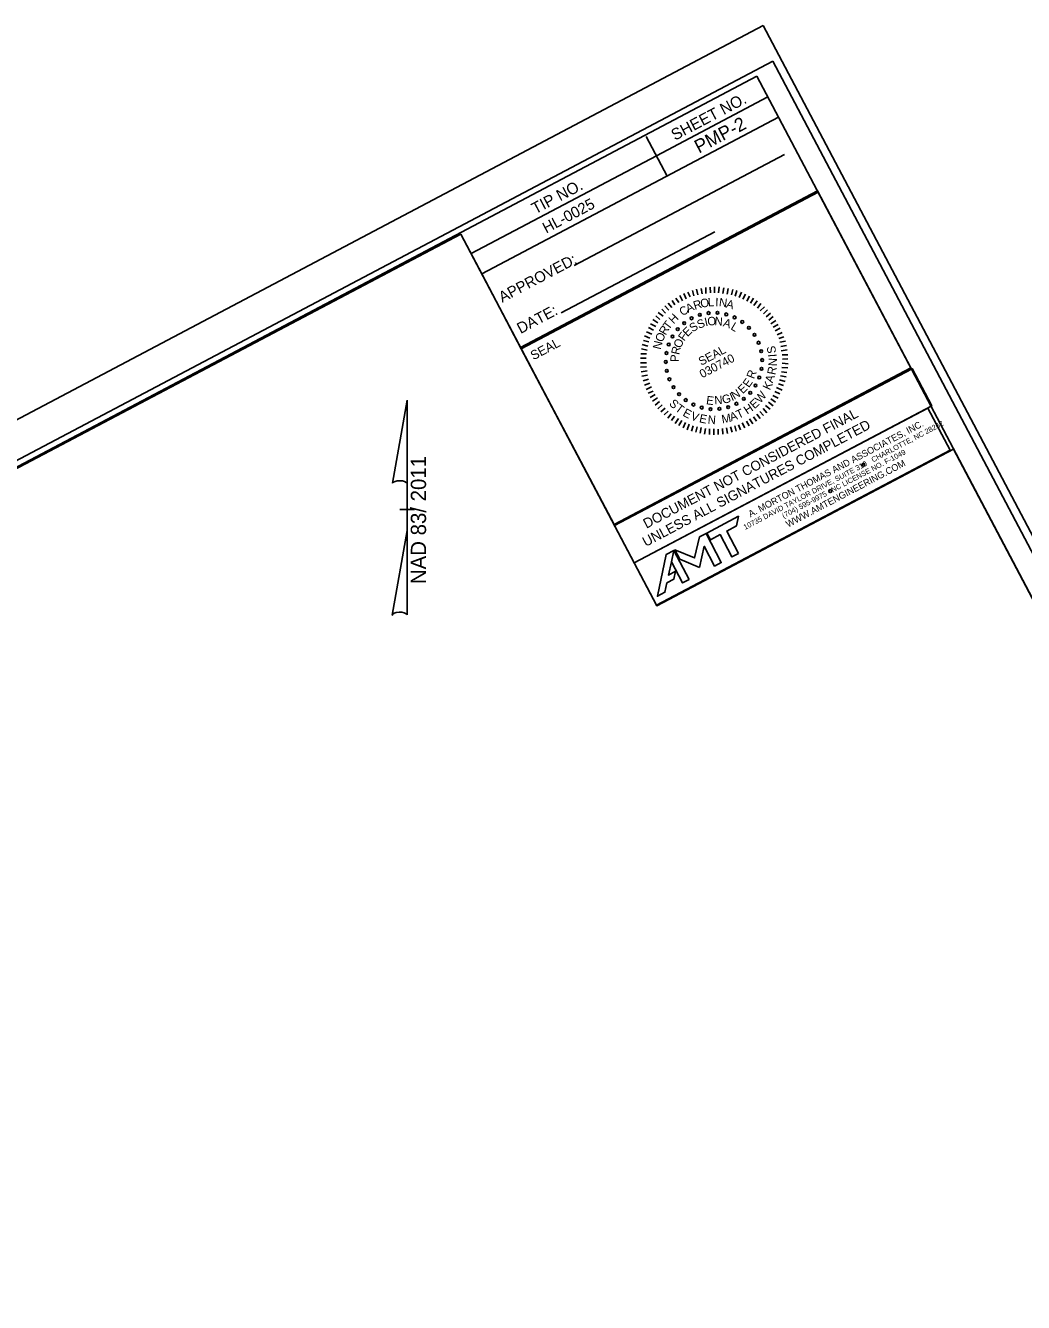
# Model space of a CAD drawing. Extents: x 1487176 to 1489663, y 497841 to 500965.
# Drawn here: x 1488420 to 1488976, y 499031 to 499742 of the extents above; entities that cross this region are included whole.
import ezdxf

# ---------------------------------------------------------------- set-up
doc = ezdxf.new("R2010")
doc.units = 0
for name, color, linetype in [('Default', 7, 'Continuous'), ('DEV TUBULAR MARKER PLAN VIEW CELL', 7, 'Continuous'), ('MARK LEFT TURN ARROW CELL', 7, 'Continuous'), ('MARK STRAIGHT ARROW CELL', 7, 'Continuous'), ('Prop Mkg Skp Wht', 7, 'Continuous'), ('Prop Mkg Solid Dbl Yel Rpm 80ft', 7, 'Continuous'), ('Prop Mkg Solid White Lane Line', 7, 'Continuous'), ('Prop Mkg Solid White Stop Bar', 7, 'Continuous'), ('Prop Paint Stripe', 7, 'Continuous'), ('Scratch_Level_1', 7, 'Continuous'), ('Scratch_Level_4', 7, 'Continuous'), ('Scratch_Level_6', 7, 'Continuous')]:
    doc.layers.add(name, color=color, linetype=linetype)

msp = doc.modelspace()

# ---------------------------------------------------------------- linework, layer by layer
at = {"layer": 'Default'}
for p, q in [((1488827.5, 499712.99), (1488827.5, 499712.99)), ((1488827.5, 499712.99), (1488827.5, 499712.99)), ((1488827.5, 499712.99), (1488827.5, 499712.99)), ((1488827.5, 499712.99), (1488827.5, 499712.99)), ((1488827.5, 499712.99), (1488827.5, 499712.99)), ((1488827.5, 499712.99), (1488827.5, 499712.99)), ((1488827.5, 499712.99), (1488827.5, 499712.99)), ((1488827.5, 499712.99), (1488827.5, 499712.99)), ((1488777.02, 499658.15), (1488765.37, 499680.23)), ((1488717.98, 499582), (1488803.58, 499627.15))]:
    msp.add_line(p, q, dxfattribs=at)
msp.add_lwpolyline([(1488695.45, 499562.62), (1488860.8, 499649.92), (1488912.82, 499551.41), (1488747.47, 499464.1)], close=True, dxfattribs=at)
at = {"layer": 'DEV TUBULAR MARKER PLAN VIEW CELL'}
msp.add_lwpolyline([(1488120.36, 498369.24), (1487949.53, 498194.25), (1487512.58, 499019.67), (1488662.1, 499625.77), (1488771.25, 499418.79), (1488936.61, 499505.98), (1489317.21, 498785.18), (1488242.69, 498217.81)], close=True, dxfattribs=at)
at = {"layer": 'MARK LEFT TURN ARROW CELL'}
msp.add_lwpolyline([(1488758.67, 499442.65), (1488922.34, 499528.95), (1488934.76, 499505.4), (1488771.09, 499419.09)], close=True, dxfattribs=at)
at = {"layer": 'MARK STRAIGHT ARROW CELL'}
msp.add_lwpolyline([(1488830.57, 499741.98), (1487342.38, 498956.18), (1487854.09, 497987.08), (1489342.28, 498772.88)], close=True, dxfattribs=at)
at = {"layer": 'Prop Mkg Skp Wht'}
msp.add_lwpolyline([(1488747.71, 499463.43), (1488913.52, 499550.87), (1488924.48, 499530.08), (1488758.67, 499442.65)], close=True, dxfattribs=at)
at = {"layer": 'Prop Mkg Solid Dbl Yel Rpm 80ft'}
for p, q in [((1488830.57, 499741.98), (1488830.57, 499741.98)), ((1488835.94, 499722.2), (1488835.94, 499722.2))]:
    msp.add_line(p, q, dxfattribs=at)
at = {"layer": 'Prop Mkg Solid White Lane Line'}
for p, q in [((1488771.08, 499669.42), (1488833.21, 499702.18)), ((1488673.74, 499603.7), (1488839.15, 499690.91)), ((1488777.02, 499658.15), (1488765.37, 499680.23)), ((1488667.8, 499614.97), (1488771.08, 499669.42)), ((1488673.74, 499603.7), (1488662.1, 499625.77)), ((1488695.75, 499561.97), (1488673.74, 499603.7))]:
    msp.add_line(p, q, dxfattribs=at)
for points in [[(1488826.93, 499713.69), (1487500.49, 499013.3), (1487990.76, 498084.79), (1489317.21, 498785.18)], [(1488695.75, 499561.97), (1488861.15, 499649.19), (1488913.11, 499550.65), (1488747.71, 499463.43)], [(1488758.67, 499442.65), (1488922.34, 499528.95), (1488934.76, 499505.4), (1488771.09, 499419.09)]]:
    msp.add_lwpolyline(points, close=True, dxfattribs=at)
for points in [[(1488816.84, 499447.97), (1488810.26, 499460.44), (1488815.64, 499463.27), (1488816.78, 499468.62), (1488799.18, 499459.33), (1488801.13, 499455.62), (1488806.55, 499458.48), (1488813.13, 499446.01), (1488816.84, 499447.97)], [(1488795.15, 499440.17), (1488797.7, 499451.99), (1488803.52, 499440.94), (1488807.23, 499442.9), (1488798.7, 499459.08), (1488794.99, 499457.13), (1488792.38, 499445.43), (1488781.32, 499449.92), (1488784.03, 499444.76), (1488795.15, 499440.17)], [(1488779.42, 499443.36), (1488780.84, 499449.67), (1488776.51, 499447.38), (1488771.6, 499424.11), (1488775.81, 499426.33), (1488776.9, 499431.55), (1488780.75, 499433.58), (1488781.78, 499438.03), (1488777.8, 499435.94), (1488779.42, 499443.36)], [(1488789.38, 499433.48), (1488780.84, 499449.67), (1488779.42, 499443.36), (1488785.66, 499431.53), (1488789.38, 499433.48)]]:
    msp.add_lwpolyline(points, dxfattribs=at)
for centre in [(1488886.42, 499497.36), (1488867.88, 499482.66)]:
    msp.add_circle(centre, 0.833, dxfattribs=at)
at = {"layer": 'Prop Mkg Solid White Stop Bar'}
for p, q in [((1488623.97, 499487.02), (1488632.17, 499533.37)), ((1488632.22, 499533.37), (1488632.17, 499533.37)), ((1488632.22, 499533.37), (1488632.17, 499533.37)), ((1488632.22, 499533.37), (1488632.22, 499485.57)), ((1488632.22, 499460.77), (1488632.22, 499486.97)), ((1488632.22, 499485.57), (1488632.22, 499486.92)), ((1488628.22, 499472.37), (1488628.17, 499472.37)), ((1488631.77, 499472.37), (1488628.22, 499472.37)), ((1488628.27, 499472.37), (1488636.27, 499472.37)), ((1488632.22, 499460.77), (1488623.87, 499413.52)), ((1488632.27, 499413.72), (1488632.22, 499460.77))]:
    msp.add_line(p, q, dxfattribs=at)
for centre, start_param, end_param in [((1488628.1, 499486.52), 0.216388, 2.908219), ((1488628.1, 499413.35), 0.201328, 3.141593)]:
    msp.add_ellipse(centre, major_axis=(4.23, -0.03), ratio=0.461098, start_param=start_param, end_param=end_param, dxfattribs=at)
at = {"layer": 'Prop Paint Stripe'}
msp.add_line((1488725.22, 499608.33), (1488842.52, 499670.19), dxfattribs=at)
at = {"layer": 'Scratch_Level_1'}
msp.add_lwpolyline([(1488835.94, 499722.2), (1487363.2, 498944.56), (1487856.23, 498010.83), (1489328.96, 498788.47)], close=True, dxfattribs=at)
at = {"layer": 'Scratch_Level_4'}
for p, q in [((1488786.37, 499592.78), (1488787.56, 499589.73)), ((1488788.65, 499593.56), (1488789.83, 499590.79)), ((1488791.14, 499594.45), (1488791.99, 499591.51)), ((1488793.48, 499595.12), (1488794.1, 499592.06)), ((1488795.93, 499595.57), (1488796.56, 499592.51)), ((1488798.6, 499596.13), (1488798.67, 499592.78)), ((1488800.95, 499596.24), (1488801.29, 499593.17)), ((1488803.4, 499596.4), (1488803.48, 499593.05)), ((1488806.09, 499596.41), (1488805.71, 499593.1)), ((1488808.61, 499595.9), (1488808.12, 499592.82)), ((1488811.08, 499595.51), (1488810.48, 499592.37)), ((1488813.61, 499595.01), (1488812.89, 499592.08)), ((1488815.92, 499594.39), (1488815.04, 499591.24)), ((1488818.4, 499593.44), (1488817.23, 499590.56)), ((1488775.79, 499585.78), (1488778.02, 499583.43)), ((1488777.66, 499587.33), (1488779.61, 499584.97)), ((1488779.8, 499588.89), (1488781.43, 499586.35)), ((1488781.85, 499590.11), (1488783.58, 499587.63)), ((1488784.05, 499591.56), (1488785.57, 499588.68)), ((1488820.77, 499592.43), (1488819.26, 499589.65)), ((1488822.92, 499591.3), (1488821.41, 499588.53)), ((1488825.13, 499590.06), (1488823.45, 499587.34)), ((1488827.28, 499588.66), (1488825.27, 499586.04)), ((1488829.16, 499587.25), (1488827.43, 499584.63)), ((1488770.66, 499580.25), (1488773, 499578.23)), ((1488772.07, 499582.12), (1488774.8, 499580.17)), ((1488774.04, 499584.01), (1488776.22, 499581.77)), ((1488831.27, 499585.39), (1488828.86, 499582.99)), ((1488833.04, 499583.64), (1488830.69, 499581.41)), ((1488834.7, 499581.83), (1488832.23, 499579.82)), ((1488836.14, 499579.91), (1488833.78, 499577.95)), ((1488765.54, 499571.46), (1488768.54, 499570.08)), ((1488766.61, 499573.72), (1488769.43, 499572.39)), ((1488767.74, 499575.87), (1488770.68, 499574.32)), ((1488769.14, 499578.31), (1488771.86, 499576.36)), ((1488837.59, 499577.7), (1488834.89, 499575.85)), ((1488838.93, 499575.44), (1488836.16, 499573.98)), ((1488840.03, 499573.34), (1488837.27, 499571.88)), ((1488763.13, 499564.25), (1488766.22, 499563.48)), ((1488763.86, 499566.62), (1488766.84, 499565.79)), ((1488764.53, 499569.09), (1488767.41, 499567.93)), ((1488841.15, 499570.96), (1488838.38, 499569.78)), ((1488842.15, 499568.52), (1488839.21, 499567.67)), ((1488842.93, 499566.25), (1488839.76, 499565.56)), ((1488762.4, 499559.21), (1488765.59, 499559.05)), ((1488762.85, 499561.84), (1488765.88, 499561.18)), ((1488843.49, 499563.85), (1488840.32, 499563.17)), ((1488843.99, 499561.29), (1488840.59, 499560.77)), ((1488844.28, 499558.62), (1488841.14, 499558.66)), ((1488762.12, 499556.79), (1488765.31, 499556.64)), ((1488762.12, 499554.11), (1488765.48, 499554.19)), ((1488762.29, 499551.65), (1488765.53, 499551.95)), ((1488844.33, 499551.29), (1488840.97, 499551.5)), ((1488844.39, 499553.59), (1488841.14, 499553.85)), ((1488844.38, 499556.27), (1488841.31, 499556.2)), ((1488762.51, 499549.09), (1488765.86, 499549.72)), ((1488762.96, 499546.64), (1488766.13, 499547.32)), ((1488763.63, 499544.02), (1488766.69, 499544.93)), ((1488764.41, 499541.75), (1488767.35, 499542.88)), ((1488842.71, 499543.65), (1488839.61, 499544.7)), ((1488843.32, 499546.24), (1488840.29, 499546.9)), ((1488843.82, 499548.77), (1488840.68, 499549.09)), ((1488765.42, 499539.31), (1488768.35, 499540.72)), ((1488766.41, 499537.15), (1488769.29, 499538.39)), ((1488767.64, 499534.83), (1488770.29, 499536.51)), ((1488838.83, 499534.4), (1488835.89, 499535.95)), ((1488839.84, 499536.77), (1488837.01, 499538.1)), ((1488841.08, 499538.97), (1488837.97, 499540.3)), ((1488841.92, 499541.4), (1488839.1, 499542.45)), ((1488768.92, 499532.68), (1488771.62, 499534.53)), ((1488770.31, 499530.58), (1488772.84, 499532.49)), ((1488771.8, 499528.55), (1488774.22, 499530.67)), ((1488773.58, 499526.8), (1488775.88, 499528.86)), ((1488832.63, 499526.32), (1488830.57, 499528.62)), ((1488834.44, 499528.26), (1488831.87, 499530.44)), ((1488836.07, 499530.25), (1488833.45, 499532.26)), ((1488837.42, 499532.24), (1488834.87, 499534.14)), ((1488775.46, 499525.11), (1488777.7, 499527.28)), ((1488777.51, 499523.36), (1488779.36, 499525.75)), ((1488779.39, 499521.95), (1488781.18, 499524.45)), ((1488781.49, 499520.38), (1488783.33, 499523.04)), ((1488783.53, 499519.19), (1488785.2, 499521.91)), ((1488822.68, 499518.94), (1488821.22, 499521.7)), ((1488824.72, 499520.16), (1488822.98, 499522.92)), ((1488826.81, 499521.55), (1488825.08, 499524.03)), ((1488828.96, 499523.11), (1488826.95, 499525.58)), ((1488830.77, 499524.77), (1488828.7, 499527.07)), ((1488786.02, 499517.96), (1488787.3, 499520.9)), ((1488788.28, 499516.89), (1488789.33, 499519.99)), ((1488790.53, 499516.1), (1488791.64, 499519.09)), ((1488793.12, 499515.49), (1488793.78, 499518.52)), ((1488795.42, 499514.87), (1488795.97, 499518.12)), ((1488797.95, 499514.37), (1488798.38, 499517.56)), ((1488800.58, 499514.2), (1488800.74, 499517.39)), ((1488803.05, 499514.09), (1488803.03, 499517.33)), ((1488805.56, 499514.14), (1488805.49, 499517.22)), ((1488808.13, 499514.37), (1488807.83, 499517.61)), ((1488810.64, 499514.7), (1488810.12, 499517.82)), ((1488813.19, 499515.49), (1488812.34, 499518.43)), ((1488815.58, 499516.04), (1488814.68, 499519.1)), ((1488817.86, 499516.82), (1488816.79, 499519.65)), ((1488820.3, 499517.83), (1488818.89, 499520.76))]:
    msp.add_line(p, q, dxfattribs=at)
for centre in [(1488790.71, 499578.94), (1488795.29, 499580.82), (1488800.15, 499581.83), (1488805.1, 499581.93), (1488809.99, 499581.12), (1488814.65, 499579.42), (1488782.95, 499572.83), (1488786.54, 499576.25), (1488818.91, 499576.89), (1488822.64, 499573.63), (1488777.92, 499564.34), (1488780.04, 499568.82), (1488825.71, 499569.73), (1488828.01, 499565.34), (1488776.66, 499559.55), (1488829.46, 499560.6), (1488776.3, 499554.6), (1488776.86, 499549.68), (1488829.65, 499550.73), (1488830.01, 499555.67), (1488778.31, 499544.94), (1488828.39, 499545.94), (1488780.61, 499540.55), (1488783.67, 499536.65), (1488823.36, 499537.44), (1488826.27, 499541.46), (1488787.4, 499533.39), (1488791.67, 499530.86), (1488796.32, 499529.16), (1488801.21, 499528.35), (1488806.17, 499528.45), (1488811.02, 499529.46), (1488815.61, 499531.34), (1488819.77, 499534.03)]:
    msp.add_circle(centre, 0.788, dxfattribs=at)
at = {"layer": 'Scratch_Level_6'}
msp.add_line((1488912.86, 499551.34), (1488747.47, 499464.1), dxfattribs=at)

# ---------------------------------------------------------------- texts
at = {"layer": 'Prop Mkg Skp Wht'}
for s, p in [('UNLESS ALL SIGNATURES COMPLETED', (1488765.12, 499451.53)), ('DOCUMENT NOT CONSIDERED FINAL', (1488765.51, 499461.68))]:
    msp.add_text(s, height=5.4995, rotation=27.80428, dxfattribs=at).set_placement(p)
at = {"layer": 'Prop Mkg Solid White Lane Line'}
for s, height, p in [('10735 DAVID TAYLOR DRIVE, SUITE 310   CHARLOTTE, NC 28262', 2.9167, (1488820.5, 499461.02)), ('A. MORTON THOMAS AND ASSOCIATES, INC.', 3.75, (1488823.49, 499468.02)), ('(704) 595-9975   NC LICENSE NO. F-1049', 2.9167, (1488841.98, 499467.41)), ('WWW.AMTENGINEERING.COM', 3.75, (1488844.42, 499462.33))]:
    msp.add_text(s, height=height, rotation=27.80428, dxfattribs=at).set_placement(p)
at = {"layer": 'Prop Mkg Solid White Stop Bar'}
msp.add_text('NAD 83/ 2011', height=8.5, rotation=90, dxfattribs=at).set_placement((1488642.74, 499430.85))
at = {"layer": 'Prop Paint Stripe'}
for s, height, p in [('SHEET NO.', 6.358, (1488781.41, 499677.75)), ('TIP NO.', 6.358, (1488703.64, 499636.75)), ('HL-0025', 6.11, (1488709.64, 499626.1)), ('APPROVED:', 6.11, (1488685.2, 499587.52)), ('DATE:', 6.11, (1488695.4, 499570.14)), ('SEAL', 5.094, (1488702.58, 499555.5))]:
    msp.add_text(s, height=height, rotation=27.79922, dxfattribs=at).set_placement(p)
at = {"layer": 'Scratch_Level_4'}
for s, height, rotation, p in [('C', 4.72, 32.77501, (1488785.65, 499579.96)), ('A', 4.72, 25.80995, (1488788.74, 499581.88)), ('R', 4.72, 17.85665, (1488792.5, 499583.58)), ('O', 4.72, 10.92189, (1488796, 499584.72)), ('L', 4.72, 3.581, (1488799.84, 499585.48)), ('I', 4.72, 358.64105, (1488803.86, 499585.62)), ('N', 4.72, 352.73893, (1488805.71, 499585.61)), ('A', 4.72, 344.84016, (1488809.58, 499584.97)), ('H', 4.72, 45.57844, (1488780.66, 499575.49)), ('S', 4.7, 20.87655, (1488794.69, 499573.01)), ('I', 4.7, 13.31716, (1488798.47, 499574.43)), ('O', 4.7, 5.70998, (1488799.69, 499574.79)), ('N', 4.7, 355.22811, (1488803.31, 499575.15)), ('A', 4.7, 341.77886, (1488807.86, 499574.58)), ('R', 4.72, 60.01054, (1488776.22, 499569.19)), ('T', 4.72, 53.27087, (1488778.05, 499572.13)), ('F', 4.7, 54.23505, (1488786.58, 499565.89)), ('E', 4.7, 44.42402, (1488788.37, 499568.39)), ('S', 4.7, 32.30312, (1488791.22, 499571.03)), ('L', 4.7, 329.3674, (1488812.08, 499573)), ('N', 4.72, 75.90175, (1488773.48, 499561.24)), ('O', 4.72, 67.77931, (1488774.46, 499565.29)), ('O', 4.7, 66.08691, (1488784.6, 499561.88)), ('P', 4.7, 87.95873, (1488783.53, 499554.53)), ('R', 4.7, 77.58289, (1488783.78, 499558.34)), ('SEAL', 4.699, 27.83509, (1488796.04, 499552.42)), ('030740', 4.699, 27.83509, (1488796.62, 499545.43)), ('S', 4.72, 100.09298, (1488837.85, 499559.76)), ('I', 4.72, 93.88149, (1488838.06, 499557.48)), ('R', 4.7, 68.18435, (1488825.4, 499544.83)), ('R', 4.72, 78.98541, (1488837.32, 499547.14)), ('N', 4.72, 87.20766, (1488838.14, 499552.16)), ('E', 4.7, 54.9919, (1488822.6, 499539.96)), ('K', 4.72, 63.9761, (1488834.24, 499538.53)), ('A', 4.72, 71.35678, (1488835.82, 499542.58)), ('E', 4.7, 352.70428, (1488798.59, 499531.1)), ('N', 4.7, 3.89345, (1488803.51, 499530.87)), ('G', 4.7, 15.31634, (1488808.32, 499531.15)), ('I', 4.7, 23.45968, (1488813.15, 499532.71)), ('N', 4.7, 30.96288, (1488814.47, 499533.41)), ('E', 4.7, 43.64078, (1488819.15, 499536.59)), ('W', 4.72, 49.84085, (1488828.96, 499531.28)), ('S', 4.72, 316.0471, (1488777.78, 499531.02)), ('T', 4.72, 323.45948, (1488781.15, 499527.83)), ('E', 4.72, 331.65758, (1488785.36, 499524.85)), ('T', 4.72, 25.22168, (1488816.8, 499522.84)), ('H', 4.72, 33.84631, (1488821.68, 499525.25)), ('E', 4.72, 41.99985, (1488825.69, 499528.19)), ('V', 4.72, 339.76489, (1488789.72, 499522.66)), ('E', 4.72, 348.06633, (1488794.64, 499521.06)), ('N', 4.72, 356.16408, (1488799.52, 499520.2)), ('M', 4.72, 10.17213, (1488807.81, 499520.33)), ('A', 4.72, 18.01726, (1488812.71, 499521.47))]:
    msp.add_text(s, height=height, rotation=rotation, dxfattribs=at).set_placement(p)
at = {"layer": 'Scratch_Level_6'}
msp.add_text('PMP-2', height=7.5, rotation=27.80344, dxfattribs=at).set_placement((1488794.75, 499670.61))

doc.saveas('drawing.dxf')
